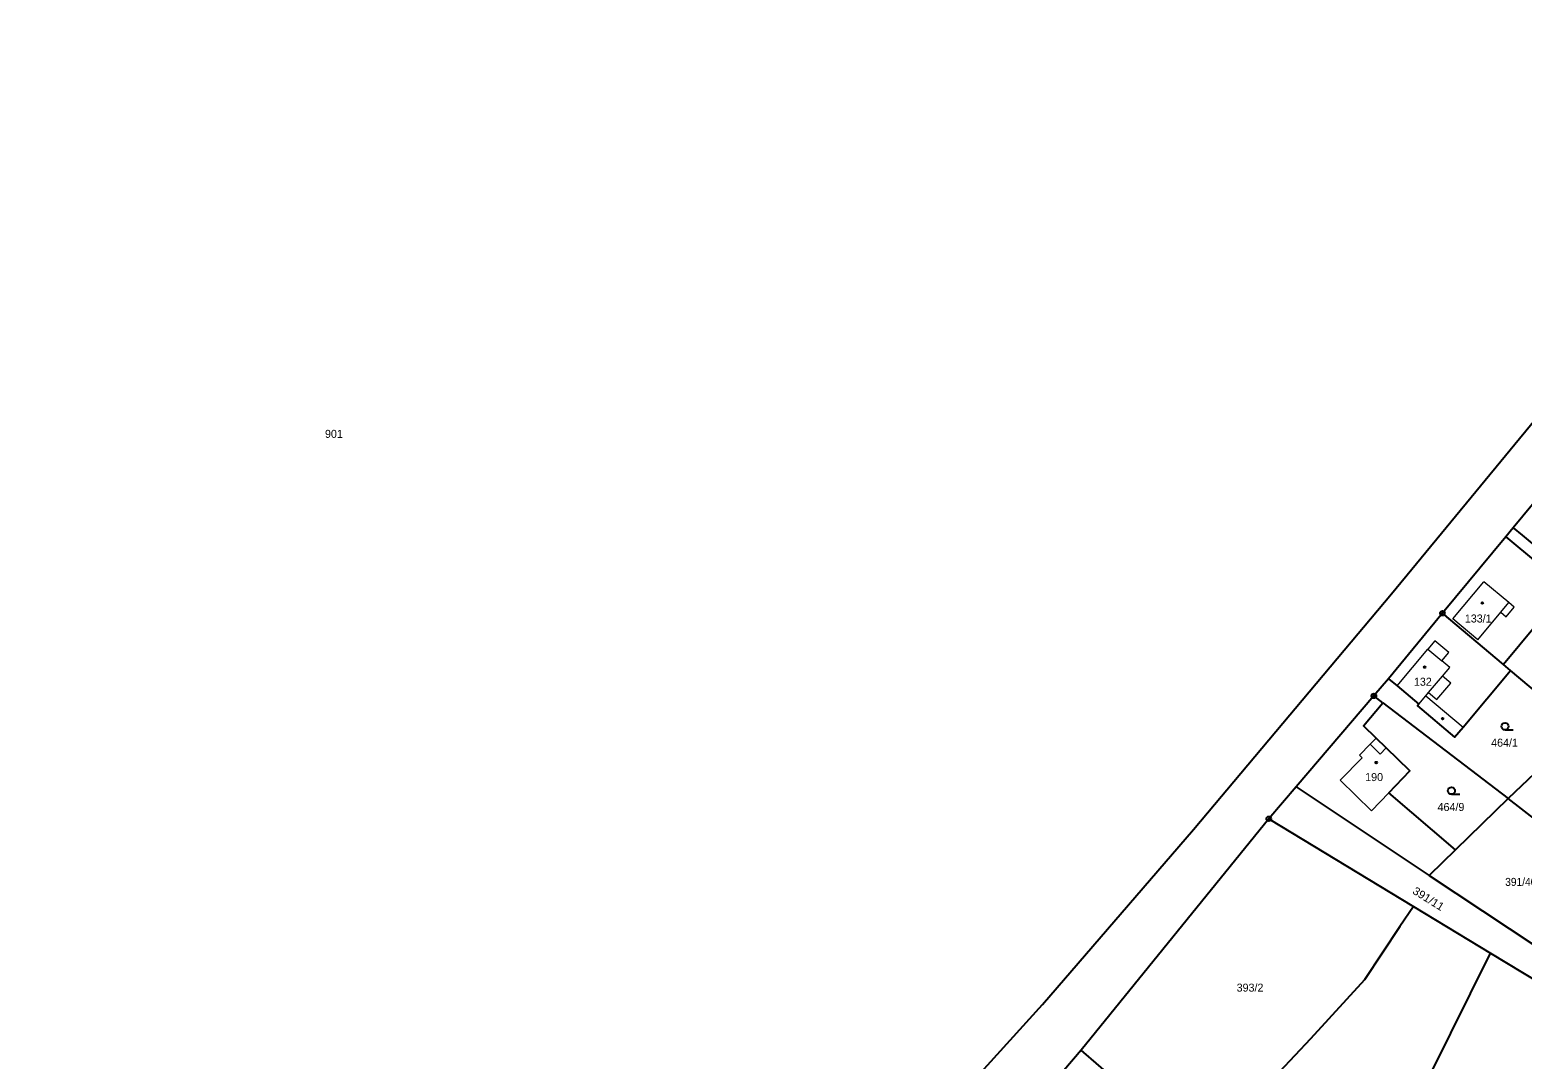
# Model space of a CAD drawing. Extents: x -758887 to -754328, y -1031688 to -1029144.
# Drawn here: x -757172.5 to -756855.4, y -1030603.7 to -1030384.9 of the extents above; entities that cross this region are included whole.
import ezdxf
from ezdxf.enums import TextEntityAlignment as Align

# ---------------------------------------------------------------- set-up
doc = ezdxf.new("R2010")
doc.units = 0
doc.header["$LTSCALE"] = 0.68
for name, color, linetype, lineweight in [('1', 7, 'Continuous', 25), ('3', 7, 'Continuous', 25), ('4', 7, 'Continuous', 13), ('5', 7, 'Continuous', 25), ('8', 7, 'Continuous', 25)]:
    doc.layers.add(name, color=color, linetype=linetype, lineweight=lineweight)
doc.layers.add('2', color=7, linetype='Continuous')

msp = doc.modelspace()

# ---------------------------------------------------------------- linework, layer by layer
at = {"layer": '1'}
for p, q in [((-756857.33, -1030490.77), (-756858.9, -1030492.67)), ((-756858.9, -1030492.67), (-756872.35, -1030508.93)), ((-756872.35, -1030508.93), (-756883.79, -1030522.84)), ((-756883.79, -1030522.84), (-756886.92, -1030526.49)), ((-756843, -1030533.68), (-756857.89, -1030521.09)), ((-756885.01, -1030527.95), (-756858.42, -1030548.27)), ((-756909.25, -1030552.61), (-756949.14, -1030601.76)), ((-756878.53, -1030571.24), (-756881.39, -1030575.53)), ((-756878.53, -1030571.24), (-756862.14, -1030581.18)), ((-756862.14, -1030581.18), (-756831.15, -1030599.97))]:
    msp.add_line(p, q, dxfattribs=at)
for points in [[(-757172.48, -1030761.99), (-757165.16, -1030751.81), (-757152.13, -1030736.25), (-757134.35, -1030719.37), (-757113.96, -1030707.3), (-757080.59, -1030692.2), (-757054.32, -1030678.02), (-757030.25, -1030661.2), (-756989.04, -1030625.89), (-756971.08, -1030607.26), (-756957.3, -1030592.11), (-756925.24, -1030554.85), (-756883.2, -1030504.8), (-756846.36, -1030460.12), (-756829.98, -1030442.25), (-756795.41, -1030407.31), (-756770.36, -1030384.93)], [(-756836.69, -1030507.85), (-756833.32, -1030501.38), (-756839.79, -1030496.51), (-756834.35, -1030489.33), (-756845.36, -1030480.04), (-756844.89, -1030479.47), (-756846.73, -1030477.94), (-756857.33, -1030490.77)], [(-756857.33, -1030490.77), (-756855.44, -1030492.33), (-756844, -1030501.79), (-756840.57, -1030504.63), (-756839.84, -1030505.24), (-756836.69, -1030507.85)], [(-756858.9, -1030492.67), (-756845.88, -1030503.51), (-756859.36, -1030519.85)], [(-756857.89, -1030521.09), (-756859.36, -1030519.85), (-756872.35, -1030508.93)], [(-756883.79, -1030522.84), (-756881.99, -1030524.35), (-756877.35, -1030528.24), (-756877.68, -1030528.62), (-756869.79, -1030535.25), (-756867.99, -1030533.11), (-756857.89, -1030521.09)], [(-756885.01, -1030527.95), (-756886.92, -1030526.49), (-756903.44, -1030545.81), (-756875.15, -1030564.63)], [(-756869.61, -1030559.21), (-756883.75, -1030547.06), (-756879.32, -1030542.45), (-756884.33, -1030537.56), (-756886.46, -1030535.48), (-756889.14, -1030532.87), (-756885.01, -1030527.95)], [(-756812.64, -1030559.04), (-756843, -1030533.68), (-756858.42, -1030548.27)], [(-756903.44, -1030545.81), (-756909.25, -1030552.61), (-756878.53, -1030571.24)], [(-756838.22, -1030563.97), (-756858.42, -1030548.27), (-756869.61, -1030559.21)], [(-756869.61, -1030559.21), (-756875.15, -1030564.63), (-756852.51, -1030579.69)], [(-756881.39, -1030575.53), (-756888.93, -1030586.85), (-756900.39, -1030599.36), (-756917.01, -1030617.08), (-756925.19, -1030618.11), (-756935.47, -1030613.62), (-756948.52, -1030602.3), (-756949.14, -1030601.76), (-756952.82, -1030606.13)], [(-756943.56, -1030666.41), (-756940.27, -1030668.25), (-756917, -1030691.76), (-756862.14, -1030581.18)]]:
    msp.add_lwpolyline(points, dxfattribs=at)
at = {"layer": '3'}
for p, q in [((-756859.063, -1030533.73), (-756857.313, -1030533.73)), ((-756870.443, -1030547.4), (-756868.693, -1030547.4))]:
    msp.add_line(p, q, dxfattribs=at)
for centre in [(-756859.0629, -1030532.9798), (-756870.4429, -1030546.6498)]:
    msp.add_circle(centre, 0.75, dxfattribs=at)
at = {"layer": '4'}
for p, q in [((-756870.13, -1030510.14), (-756863.56, -1030502.23)), ((-756858.25, -1030506.64), (-756863.56, -1030502.23)), ((-756859.98, -1030508.72), (-756858.25, -1030506.64)), ((-756864.82, -1030514.55), (-756870.13, -1030510.14)), ((-756881.99, -1030524.35), (-756875.44, -1030516.55)), ((-756873.96, -1030514.79), (-756875.44, -1030516.55)), ((-756875.44, -1030516.55), (-756872.49, -1030519.03)), ((-756871.01, -1030517.26), (-756873.96, -1030514.79)), ((-756872.49, -1030519.03), (-756871.01, -1030517.26)), ((-756870.81, -1030520.44), (-756872.49, -1030519.03)), ((-756872.35, -1030522.28), (-756870.81, -1030520.44)), ((-756875.31, -1030525.8), (-756872.35, -1030522.28)), ((-756873.54, -1030527.28), (-756870.59, -1030523.76)), ((-756870.59, -1030523.76), (-756872.35, -1030522.28)), ((-756877.35, -1030528.24), (-756875.88, -1030526.48)), ((-756875.88, -1030526.48), (-756875.31, -1030525.8)), ((-756875.88, -1030526.48), (-756867.99, -1030533.11)), ((-756875.31, -1030525.8), (-756873.54, -1030527.28)), ((-756886.46, -1030535.48), (-756887.72, -1030536.77)), ((-756889.45, -1030539.62), (-756894.12, -1030544.42)), ((-756887.72, -1030536.77), (-756889.99, -1030539.1)), ((-756889.99, -1030539.1), (-756889.45, -1030539.62))]:
    msp.add_line(p, q, dxfattribs=at)
for points in [[(-756864.82, -1030514.55), (-756859.98, -1030508.72), (-756858.82, -1030509.67), (-756857.1, -1030507.6), (-756858.25, -1030506.64)], [(-756884.33, -1030537.56), (-756885.59, -1030538.85), (-756887.72, -1030536.77)], [(-756883.75, -1030547.06), (-756887.46, -1030550.91), (-756894.12, -1030544.42)]]:
    msp.add_lwpolyline(points, dxfattribs=at)
at = {"layer": '5'}
for centre in [(-756863.8868, -1030506.7392), (-756876.1268, -1030520.3792), (-756872.3268, -1030531.3292), (-756886.4368, -1030540.6592)]:
    msp.add_circle(centre, 0.175, dxfattribs=at)
at = {"layer": '8'}
for centre, radius in [((-756872.35, -1030508.9299), 0.5), ((-756872.35, -1030508.9299), 0.0303), ((-756886.92, -1030526.4899), 0.5), ((-756886.92, -1030526.4899), 0.0303), ((-756909.25, -1030552.6099), 0.5), ((-756909.25, -1030552.6099), 0.0303)]:
    msp.add_circle(centre, radius, dxfattribs=at)

# ---------------------------------------------------------------- texts
at = {"layer": '2'}
for s, p in [('901', (-757107.879, -1030471.646)), ('133/1', (-756864.76, -1030510.89)), ('132', (-756876.519, -1030524.33)), ('464/1', (-756859.17, -1030537.28)), ('190', (-756886.879, -1030544.59)), ('464/9', (-756870.55, -1030550.95)), ('393/2', (-756913.24, -1030589.34))]:
    msp.add_text(s, height=1.7, dxfattribs=at).set_placement(p, align=Align.CENTER)
at = {"layer": '2', "width": 0.95}
msp.add_text('391/40', height=1.7, dxfattribs=at).set_placement((-756855.719, -1030566.87), align=Align.CENTER)
at = {"layer": '2', "width": 1.05}
msp.add_text('391/11', height=1.7, rotation=328, dxfattribs=at).set_placement((-756875.7794, -1030570.3183), align=Align.CENTER)

doc.saveas('drawing.dxf')
